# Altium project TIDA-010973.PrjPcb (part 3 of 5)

## Sheet TIDA-010973_SystemPower.SchDoc
size 431 x 279 mm; Date: Not shown in title block; ApprovedBy: Not shown in title block; CheckedBy: Not shown in title block; Author: Not shown in title block; CompanyName: Not shown in title block; Engineer: Not shown in title block; Organization: Not shown in title block; Address1: Not shown in title block; Address2: Not shown in title block; Address3: Not shown in title block; Address4: Not shown in title block; DocumentNumber: 2; Revision: Use project parameter SCH_Rev; SheetNumber: 7; SheetTotal: 15; PageSetup: Record=PageOptions¦CenterHorizontal=True¦CenterVertical=True¦PrintScale=1.00¦XCorrection=1.00¦YCorrection=1.00¦PrintKind=0¦BorderSize=5000000¦LeftOffset=0¦BottomOffset=0¦Orientation=2¦PaperLength=1000¦PaperWidth=1000¦Scale=100¦PaperSource=15¦PrintQuality=600¦MediaType=1¦DitherType=10¦PaperKind=Letter¦PrintScaleMode=1
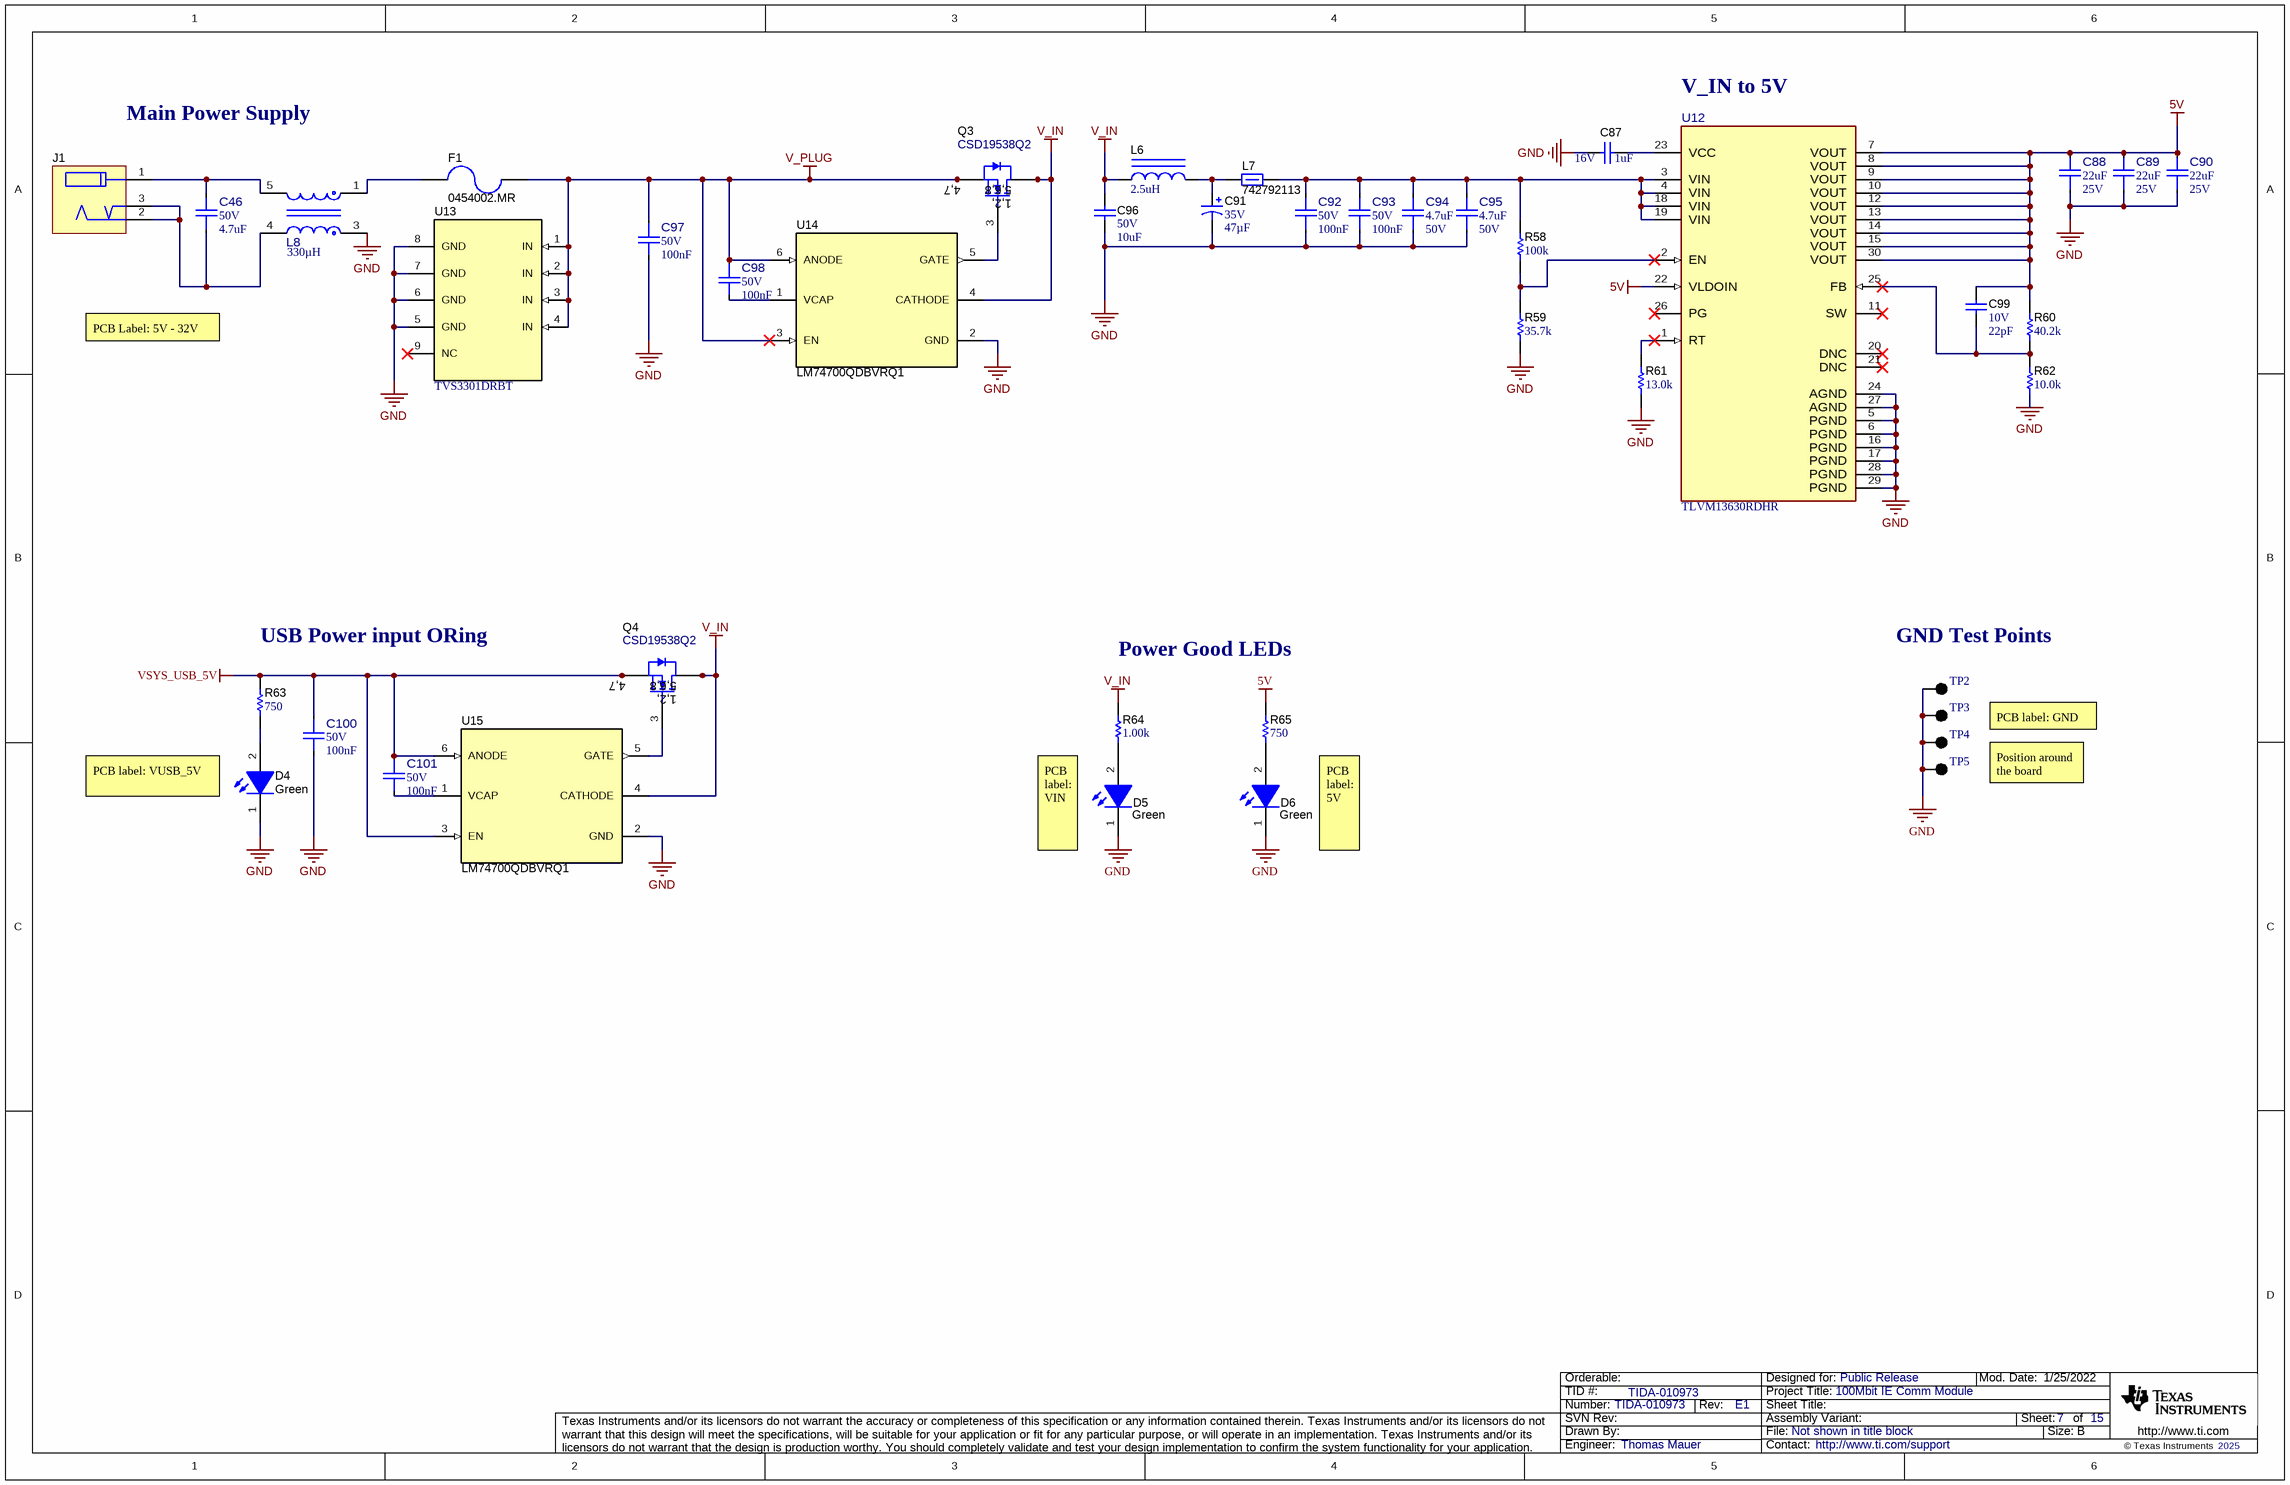
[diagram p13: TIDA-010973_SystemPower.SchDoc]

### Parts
C46  VDC_V: 50V  ValueDisplayed: 4.7uF  [FP-885012208094_1206-MFG]  (hidden comment: 885012208094)
C87  VDC_V: 16V  ValueDisplayed: 1uF  [0402L]  (hidden comment: EMK105BJ105KVHF)
C88  ValueDisplayed: 22uF  VDC_V: 25V  [FP-885012209074_1210-IPC_C]  (hidden comment: 885012209074)
C89  ValueDisplayed: 22uF  VDC_V: 25V  [FP-885012209074_1210-IPC_C]  (hidden comment: 885012209074)
C90  ValueDisplayed: 22uF  VDC_V: 25V  [FP-885012209074_1210-IPC_C]  (hidden comment: 885012209074)
C91  VDC_V: 35V  ValueDisplayed: 47µF  [Panasonic_SMT_630x580]  (hidden comment: EEE-FP1V470AP)
C92  VDC_V: 50V  ValueDisplayed: 100nF  [FP-885012205086_0402-IPC_C]  (hidden comment: 885012205086)
C93  VDC_V: 50V  ValueDisplayed: 100nF  [FP-885012205086_0402-IPC_C]  (hidden comment: 885012205086)
C94  ValueDisplayed: 4.7uF  VDC_V: 50V  [FP-885012209048_1210-IPC_C]  (hidden comment: 885012209048)
C95  ValueDisplayed: 4.7uF  VDC_V: 50V  [FP-885012209048_1210-IPC_C]  (hidden comment: 885012209048)
C96  VDC_V: 50V  ValueDisplayed: 10uF  [1210_270L]  (hidden comment: GRM32ER71H106KA12L)
C97  VDC_V: 50V  ValueDisplayed: 100nF  [FP-885012205086_0402-IPC_A]  (hidden comment: 885012205086)
C98  VDC_V: 50V  ValueDisplayed: 100nF  [FP-885012205086_0402-MFG]  (hidden comment: 885012205086)
C99  VDC_V: 10V  ValueDisplayed: 22pF  [0402L]  (hidden comment: 885012005009)
C100  VDC_V: 50V  ValueDisplayed: 100nF  [FP-885012205086_0402-IPC_C]  (hidden comment: 885012205086)
C101  VDC_V: 50V  ValueDisplayed: 100nF  [FP-885012205086_0402-IPC_C]  (hidden comment: 885012205086)
D4  value Green  [WL-SMCW_GREEN]  (hidden comment: 150060VS75000)
D5  value Green  [WL-SMCW_GREEN]  (hidden comment: 150060VS75000)
D6  value Green  [WL-SMCW_GREEN]  (hidden comment: 150060VS75000)
F1  0454002.MR  [SloBlo452]
J1  PJ-102AH  [CUI_PJ-102AH]  (value not drawn)
L6  ValueDisplayed: 2.5uH  [WE-TPC-S]  (hidden comment: 744031002)
L7  742792113  [1206L]
L8  Ind_H: 330µH  [FP-744212331_SMT_CMC_6MM5_3MM6-MFG]  (hidden comment: 744212331)
Q3  CSD19538Q2  [DQK0006C]
Q4  CSD19538Q2  [DQK0006C]
R58  ValueDisplayed: 100k  [0402L]  (hidden comment: CRCW0402100KFKED)
R59  ValueDisplayed: 35.7k  [0402L]  (hidden comment: CRCW040235K7FKED)
R60  ValueDisplayed: 40.2k  [0402L]  (hidden comment: CRCW040240K2FKED)
R61  ValueDisplayed: 13.0k  [0402L]  (hidden comment: CRCW040213K0FKED)
R62  ValueDisplayed: 10.0k  [0402L]  (hidden comment: CRCW040210K0DHEDP)
R63  ValueDisplayed: 750  [0402L]  (hidden comment: CRCW0402750RFKED)
R64  ValueDisplayed: 1.00k  [0402L]  (hidden comment: CRCW04021K00FKED)
R65  ValueDisplayed: 750  [0402L]  (hidden comment: CRCW0402750RFKED)
TP2  5011  [Keystone5011]  (value not drawn)
TP3  5011  [Keystone5011]  (value not drawn)
TP4  5011  [Keystone5011]  (value not drawn)
TP5  5011  [Keystone5011]  (value not drawn)
U12  TLVM13630RDHR  [RDH0030A-MFG]
U13  TVS3301DRBT  [DRB0008A]
U14  LM74700QDBVRQ1  [DBV0006A_L]
U15  LM74700QDBVRQ1  [DBV0006A_N]

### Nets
5V: C88.2 C89.2 C90.2 C99.1 R60.2 R65.2 U12.7(VOUT) U12.8(VOUT) U12.9(VOUT) U12.10(VOUT) U12.12(VOUT) U12.13(VOUT) U12.14(VOUT) U12.15(VOUT) U12.22(VLDOIN) U12.30(VOUT)
GND: C87.2 C88.1 C89.1 C90.1 C91.2(-) C92.1 C93.1 C94.1 C95.1 C96.2 C97.2 C100.2 D4.1(K) D5.1(K) D6.1(K) L8.3 R59.1 R61.1 R62.1 TP2.1 TP3.1 TP4.1 TP5.1 U12.5(PGND) U12.6(PGND) U12.16(PGND) U12.17(PGND) U12.24(AGND) U12.27(AGND) U12.28(PGND) U12.29(PGND) U13.5(GND) U13.6(GND) U13.7(GND) U13.8(GND) U14.2(GND) U15.2(GND)
V_IN: C96.1 L6.1 Q3.1(D) Q3.2(D) Q3.5(D) Q3.6(D) Q3.8(D) Q4.1(D) Q4.2(D) Q4.5(D) Q4.6(D) Q4.8(D) R64.2 U14.4(CATHODE) U15.4(CATHODE)
V_PLUG: C97.1 C98.1 F1.1 Q3.4(S) Q3.7(S) U13.1(IN) U13.2(IN) U13.3(IN) U13.4(IN) U14.3(EN) U14.6(ANODE)
VSYS_USB_5V: C100.1 C101.1 Q4.4(S) Q4.7(S) R63.2 U15.3(EN) U15.6(ANODE)
NetC46_1: C46.1 J1.2 J1.3 L8.4
NetC46_2: C46.2 J1.1 L8.5
NetC87_1: C87.1 U12.23(VCC)
NetC91_1: C91.1(+) L6.2 L7.1
NetC92_2: C92.2 C93.2 C94.2 C95.2 L7.2 R58.2 U12.3(VIN) U12.4(VIN) U12.18(VIN) U12.19(VIN)
NetC98_2: C98.2 U14.1(VCAP)
NetC99_2: C99.2 R60.1 R62.2 U12.25(FB)
NetC101_2: C101.2 U15.1(VCAP)
NetD4_2: D4.2(A) R63.1
NetD5_2: D5.2(A) R64.1
NetD6_2: D6.2(A) R65.1
NetF1_2: F1.2 L8.1
NetQ3_3: Q3.3(G) U14.5(GATE)
NetQ4_3: Q4.3(G) U15.5(GATE)
NetR58_1: R58.1 R59.2 U12.2(EN)
NetR61_2: R61.2 U12.1(RT)

Not connected (* = marked no-connect by the designer): U12 11(SW)* 20(DNC)* 21(DNC)* 26(PG)*; U13 9(NC)*

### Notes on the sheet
- V_IN to 5V
- Main Power Supply
- PCB Label: 5V - 32V
- (near R63) USB Power input ORing
- Power Good LEDs
- (near TP2) GND Test Points
- PCB label: GND
- PCB label: VUSB_5V
- Position around the board
- PCB label: VIN
- PCB label: 5V

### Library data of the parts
C46 = CMP-0088282-2: 4.7µF ±10% 50V Ceramic Capacitor X7R 1206 (3216 Metric); Manufacturer: Wurth Electronics; TempCo: 15%; Symbol Name: SYM-885012208094; SizeZ_mm: 1.9mm; AEC Qualified: No
C87 = CMP-0006347-2: CAP, CERM, 1 uF, 16 V, +/- 10%, X5R, 0402; Manufacturer: Taiyo Yuden; TaMin_C: -55°C; Polarized: N; SizeAreaWB_mm2: 3; Value1: Unknown; U/M: EA; Value: 1uF; TaMax_C: 85°C; SizeZ_mm: 0.6; SizeX_mm: 1; SizeY_mm: 0.5; Cap_Case: 0402; Cap_F: 1µF; AEC Category: Q200
C88-C90 = CMP-0096740-1: 22 µF ±10% 25V Ceramic Capacitor X7R 1210 (3225 Metric); Manufacturer: Wurth; AEC Qualified: No; Cap_F: 22µF; SizeZ_mm: 2.7mm; Value: 22µF; TempCo: 15%
C91 = CMP-0076702-1: CAP, AL, 47 µF, 35 V, +/- 20%, 0.26 ohm, AEC-Q200 Grade 2, SMD; Manufacturer: Panasonic; IRMS_A: 300mA; SizeAreaWB_mm2: 84.28; SizeArea_mm2: 51.48; AEC Qualified: Y; AEC Category: Q200; Value: 47uF; TaMax_C: 105°C; SizeZ_mm: 6.1; AEC Grade: 2; TaMin_C: -55°C; SizeY_mm: 6.6; U/M: EA; CompType: Capacitor; SizeX_mm: 7.8; ESR_ohm: 0.26; Cap_Case: 6.3x5.8mm
C92 C93 C97 C98 C100 C101 = CMP-0096737-1: 100 nF ±10% 50V Ceramic Capacitor X7R 0402 (1005 Metric); Manufacturer: Wurth; SizeZ_mm: 0.7mm; TempCo: 15%; AEC Qualified: No; Value: 100nF
C94 C95 = CMP-0096739-1: 4.7 µF ±10% 50V Ceramic Capacitor X7R 1210 (3225 Metric); Manufacturer: Wurth; TempCo: 15%; Cap_F: 4.7µF; AEC Qualified: No; SizeZ_mm: 2.7mm; Value: 4.7µF
C96 = CMP-0009226-3: CAP, CERM, 10 uF, 50 V, +/- 10%, X7R, 1210; Manufacturer: MuRata; TaMin_C: -55°C; Polarized: N; SizeAreaWB_mm2: 14.7; Value1: Unknown; U/M: EA; Value: 10uF; TaMax_C: 125°C; SizeZ_mm: 2.7; SizeX_mm: 3.2; SizeY_mm: 2.5; Cap_Case: 1210; SizeArea_mm2: 8; Cap_F: 10µF; AEC Category: Q200
C99 = CMP-0064912-2: CAP, CERM, 22 pF, 10 V,+/- 5%, C0G/NP0, 0402; Manufacturer: Wurth Elektronik; TaMin_C: -55°C; Polarized: N; SizeAreaWB_mm2: 3; Value1: Unknown; U/M: EA; Value: 22pF; TaMax_C: 125°C; SizeZ_mm: 0.6; SizeX_mm: 1; SizeY_mm: 0.5; Cap_Case: 0402; AEC Category: Q200
D4-D6 = CMP-0002894-2: LED, Green, SMD; Manufacturer: Wurth Elektronik; Type: AlInGaP; Value2: 2V; Io_A: 20mA; Value1: W
F1 = CMP-0003484-2: Fuse, 2 A, 125VAC/VDC, SMD; Manufacturer: Littelfuse; Irating_A: 2A; Interrupt_AC: 50A; VAC_V: 125V; Rtyp_Ohm: 62.5m; MeltingTyp: 8.2
J1 = CMP-0075222-1: DC POWER JACK, R/A, TH; Manufacturer: CUI Inc.; CNHeader: False; Current_A: 5A; Green_Lifecycle: Not Set; Gender: Male; Green_REACh: Incomplete; Voltage_V: 24V; Cert_UL: Y
L6 = CMP-0063784-1: Inductor, Shielded Drum Core, Ferrite, 2.5 uH, 1.25 A, 0.05 ohm, SMD; Manufacturer: Wurth Elektronik; Isat: 1.25A @ 35% inductance drop; Irms: 1.45A @ 30C rise; Green_Lifecycle: Active; SizeAreaWB_mm2: 23.04; DCR_ohm: 50m; Green_REACh: Passed; Value: 2.5uH; Imax_A: 1.25A; SizeZ_mm: 1.65; SizeX_mm: 3.8; SizeArea_mm2: 14.44; Ind_H: 2.5µH; AEC Category: Q200
L7 = CMP-0003112-1: Ferrite Bead, 120 ohm @ 100 MHz, 3 A, 1206; Manufacturer: Wurth Elektronik; Ztyp@1GHz_Ohm: 136.787; ZTyp@100MHz_Ohm: 120; SizeAreaWB_mm2: 10.92; DCR_ohm: 0.03; Value1: 0.03 ohm; Value: 120 ohm; Imax_A: 3A; SizeZ_mm: 1.35; SizeX_mm: 3.2; SizeY_mm: 1.6; SizeArea_mm2: 5.12
L8 = CMP-0127118-1: 330 µH @ 100 kHz 2 Line Common Mode Choke Surface Mount 2 kOhms @ 20 MHz 300mA DCR 300mOhm; Manufacturer: Wurth Electronics; AEC Qualified: No; DCR_ohm: 0.3; SizeZ_mm: 1.8mm; TaMax_C: +85°C; TaMin_C: -40°C; Test Frequency: 10kHz; Tolerance_%: 50%
Q3 Q4 = CMP-0000968-2: MOSFET, N-CH, 100 V, 4.5 A, DQK0006C (WSON-6); Alternate Manufacturer: None; Manufacturer: Texas Instruments; SizeZ_mm: 0.8; ChType: N; VdsMax_V: 100V; SizeX_mm: 2; SizeAreaWB_mm2: 9; Vgs_V: 20V; Value: 100V; SizeArea_mm2: 4; AEC Category: Q101; IdsMax_A: 4.5A; U/M: EA
R58 = CMP-0025950-3: RES, 100 k, 1%, 0.063 W, AEC-Q200 Grade 0, 0402; Manufacturer: Vishay-Dale; Power_W: 63mW; TempCo: 100 ppm/C; Value: 100k; EIA_Code: E96; SizeX_mm: 1; SizeY_mm: 0.5; SizeZ_mm: 0.6; Value2: 0.063W; AEC Qualified: Y; VDC_V: 50V; AEC Category: Q200; AEC Grade: 0
R59 = CMP-0026310-2: RES, 35.7 k, 1%, 0.063 W, AEC-Q200 Grade 0, 0402; Manufacturer: Vishay-Dale; Power_W: 63mW; TempCo: 100 ppm/C; Value_Code: 35k7; Value: 35.7k; EIA_Code: E96; SizeX_mm: 1; SizeY_mm: 0.5; SizeZ_mm: 0.6; Value2: 0.063W; AEC Qualified: Y; VDC_V: 50V; AEC Category: Q200; AEC Grade: 0
R60 = CMP-0026367-2: RES, 40.2 k, 1%, 0.063 W, AEC-Q200 Grade 0, 0402; Manufacturer: Vishay-Dale; Power_W: 63mW; TempCo: 100 ppm/C; Value_Code: 40k2; Value: 40.2k; EIA_Code: E96; SizeX_mm: 1; SizeY_mm: 0.5; SizeZ_mm: 0.6; Value2: 0.063W; AEC Qualified: Y; VDC_V: 50V; AEC Category: Q200; AEC Grade: 0
R61 = CMP-0026003-3: RES, 13.0 k, 1%, 0.063 W, AEC-Q200 Grade 0, 0402; Manufacturer: Vishay-Dale; Power_W: 63mW; TempCo: 100 ppm/C; Value_Code: 13k0; Value: 13.0k; EIA_Code: E96; Res_ohm: 13k; SizeX_mm: 1; SizeY_mm: 0.5; SizeZ_mm: 0.6; Value2: 0.063W; AEC Qualified: Y; VDC_V: 50V; AEC Category: Q200; AEC Grade: 0
R62 = CMP-0026769-2: RES, 10.0 k, 0.5%, 0.063 W, AEC-Q200 Grade 0, 0402; Manufacturer: Vishay-Dale; Power_W: 63mW; TempCo: 50 ppm/C; Value_Code: 10k0; Value: 10.0k; EIA_Code: E192; Res_ohm: 10k; SizeX_mm: 1; SizeY_mm: 0.5; SizeZ_mm: 0.6; Value2: 0.063W; AEC Qualified: Y; VDC_V: 50V; AEC Category: Q200; AEC Grade: 0
R63 R65 = CMP-0026542-2: RES, 750, 1%, 0.063 W, AEC-Q200 Grade 0, 0402; Manufacturer: Vishay-Dale; Power_W: 63mW; TempCo: 100 ppm/C; Value_Code: 750R; Value: 750; EIA_Code: E96; SizeX_mm: 1; SizeY_mm: 0.5; SizeZ_mm: 0.6; Value2: 0.063W; AEC Qualified: Y; VDC_V: 50V; AEC Grade: 0; AEC Category: Q200
R64 = CMP-0026071-3: RES, 1.00 k, 1%, 0.063 W, AEC-Q200 Grade 0, 0402; Manufacturer: Vishay-Dale; Power_W: 63mW; TempCo: 100 ppm/C; Value_Code: 1k00; Value: 1.00k; EIA_Code: E96; Res_ohm: 1k; SizeX_mm: 1; SizeY_mm: 0.5; SizeZ_mm: 0.6; Value2: 0.063W; AEC Qualified: Y; VDC_V: 50V; AEC Category: Q200; AEC Grade: 0
TP2-TP5 = CMP-0055148-2: Test Point, Multipurpose, Black, TH; Manufacturer: Keystone Electronics; CNHeader: FALSE; ContactFinish: Silver; Green_REACh: Passed; Green_Lifecycle: Active; CT: TRUE
U12 = CMP-0092030-4: 3-V to 36-V Input, 1-V to 6-V Output, 3-A Power Module; Manufacturer: Texas Instruments; Max Supply Voltage: 36V; Standoff Height: 0mm; AEC Qualified: No; CompType: IC; Min Supply Voltage: 3V; Switching Topology: Buck; AEC Category: Q200; TaMin_C: -40°C; TaMax_C: +105°C; Output Voltage: 1-6V; Switching Frequency: 200-2200kHz; Output Type: AdjustableProgrammable; SizeZ_mm: 1.9mm; Number Of Outputs: 1
U13 = CMP-0081714-3: 33 V Bidirectional Flat-Clamp Surge Protection Device, DRB0008A (VSON-8); Manufacturer: Texas Instruments; Alternate PartNumber: TVS3301DRBR; CompType: IC; SizeAreaWB_mm2: 16.0; SizeY_mm: 3.0; Rating: Catalog; AEC Category: Q200; AEC Qualified: N; SizeArea_mm2: 9.0; SizeZ_mm: 1.0
U14 U15 = CMP-0013281-4: Low Iq Always ON Smart Diode Controller, DBV0006A (SOT-23-6); Alternate PartNumber: LM74700QDBVTQ1; Manufacturer: Texas Instruments; SizeZ_mm: 1.45; SizeX_mm: 2.8; SizeY_mm: 2.9; SizeArea_mm2: 8.12; CompType: IC; SizeAreaWB_mm2: 14.82; AEC Category: Q200; AEC Qualified: Y

## Sheet TIDA-010973_SystemLED.SchDoc
size 431 x 279 mm; Date: Not shown in title block; ApprovedBy: Not shown in title block; CheckedBy: Not shown in title block; Author: Not shown in title block; CompanyName: Not shown in title block; Engineer: Not shown in title block; Organization: Not shown in title block; Address1: Not shown in title block; Address2: Not shown in title block; Address3: Not shown in title block; Address4: Not shown in title block; DocumentNumber: 2; Revision: Use project parameter SCH_Rev; SheetNumber: 10; SheetTotal: 15; PageSetup: Record=PageOptions¦CenterHorizontal=True¦CenterVertical=True¦PrintScale=1.00¦XCorrection=1.00¦YCorrection=1.00¦PrintKind=0¦BorderSize=5000000¦LeftOffset=0¦BottomOffset=0¦Orientation=2¦PaperLength=1000¦PaperWidth=1000¦Scale=100¦PaperSource=15¦PrintQuality=600¦MediaType=1¦DitherType=10¦PaperKind=Letter¦PrintScaleMode=1
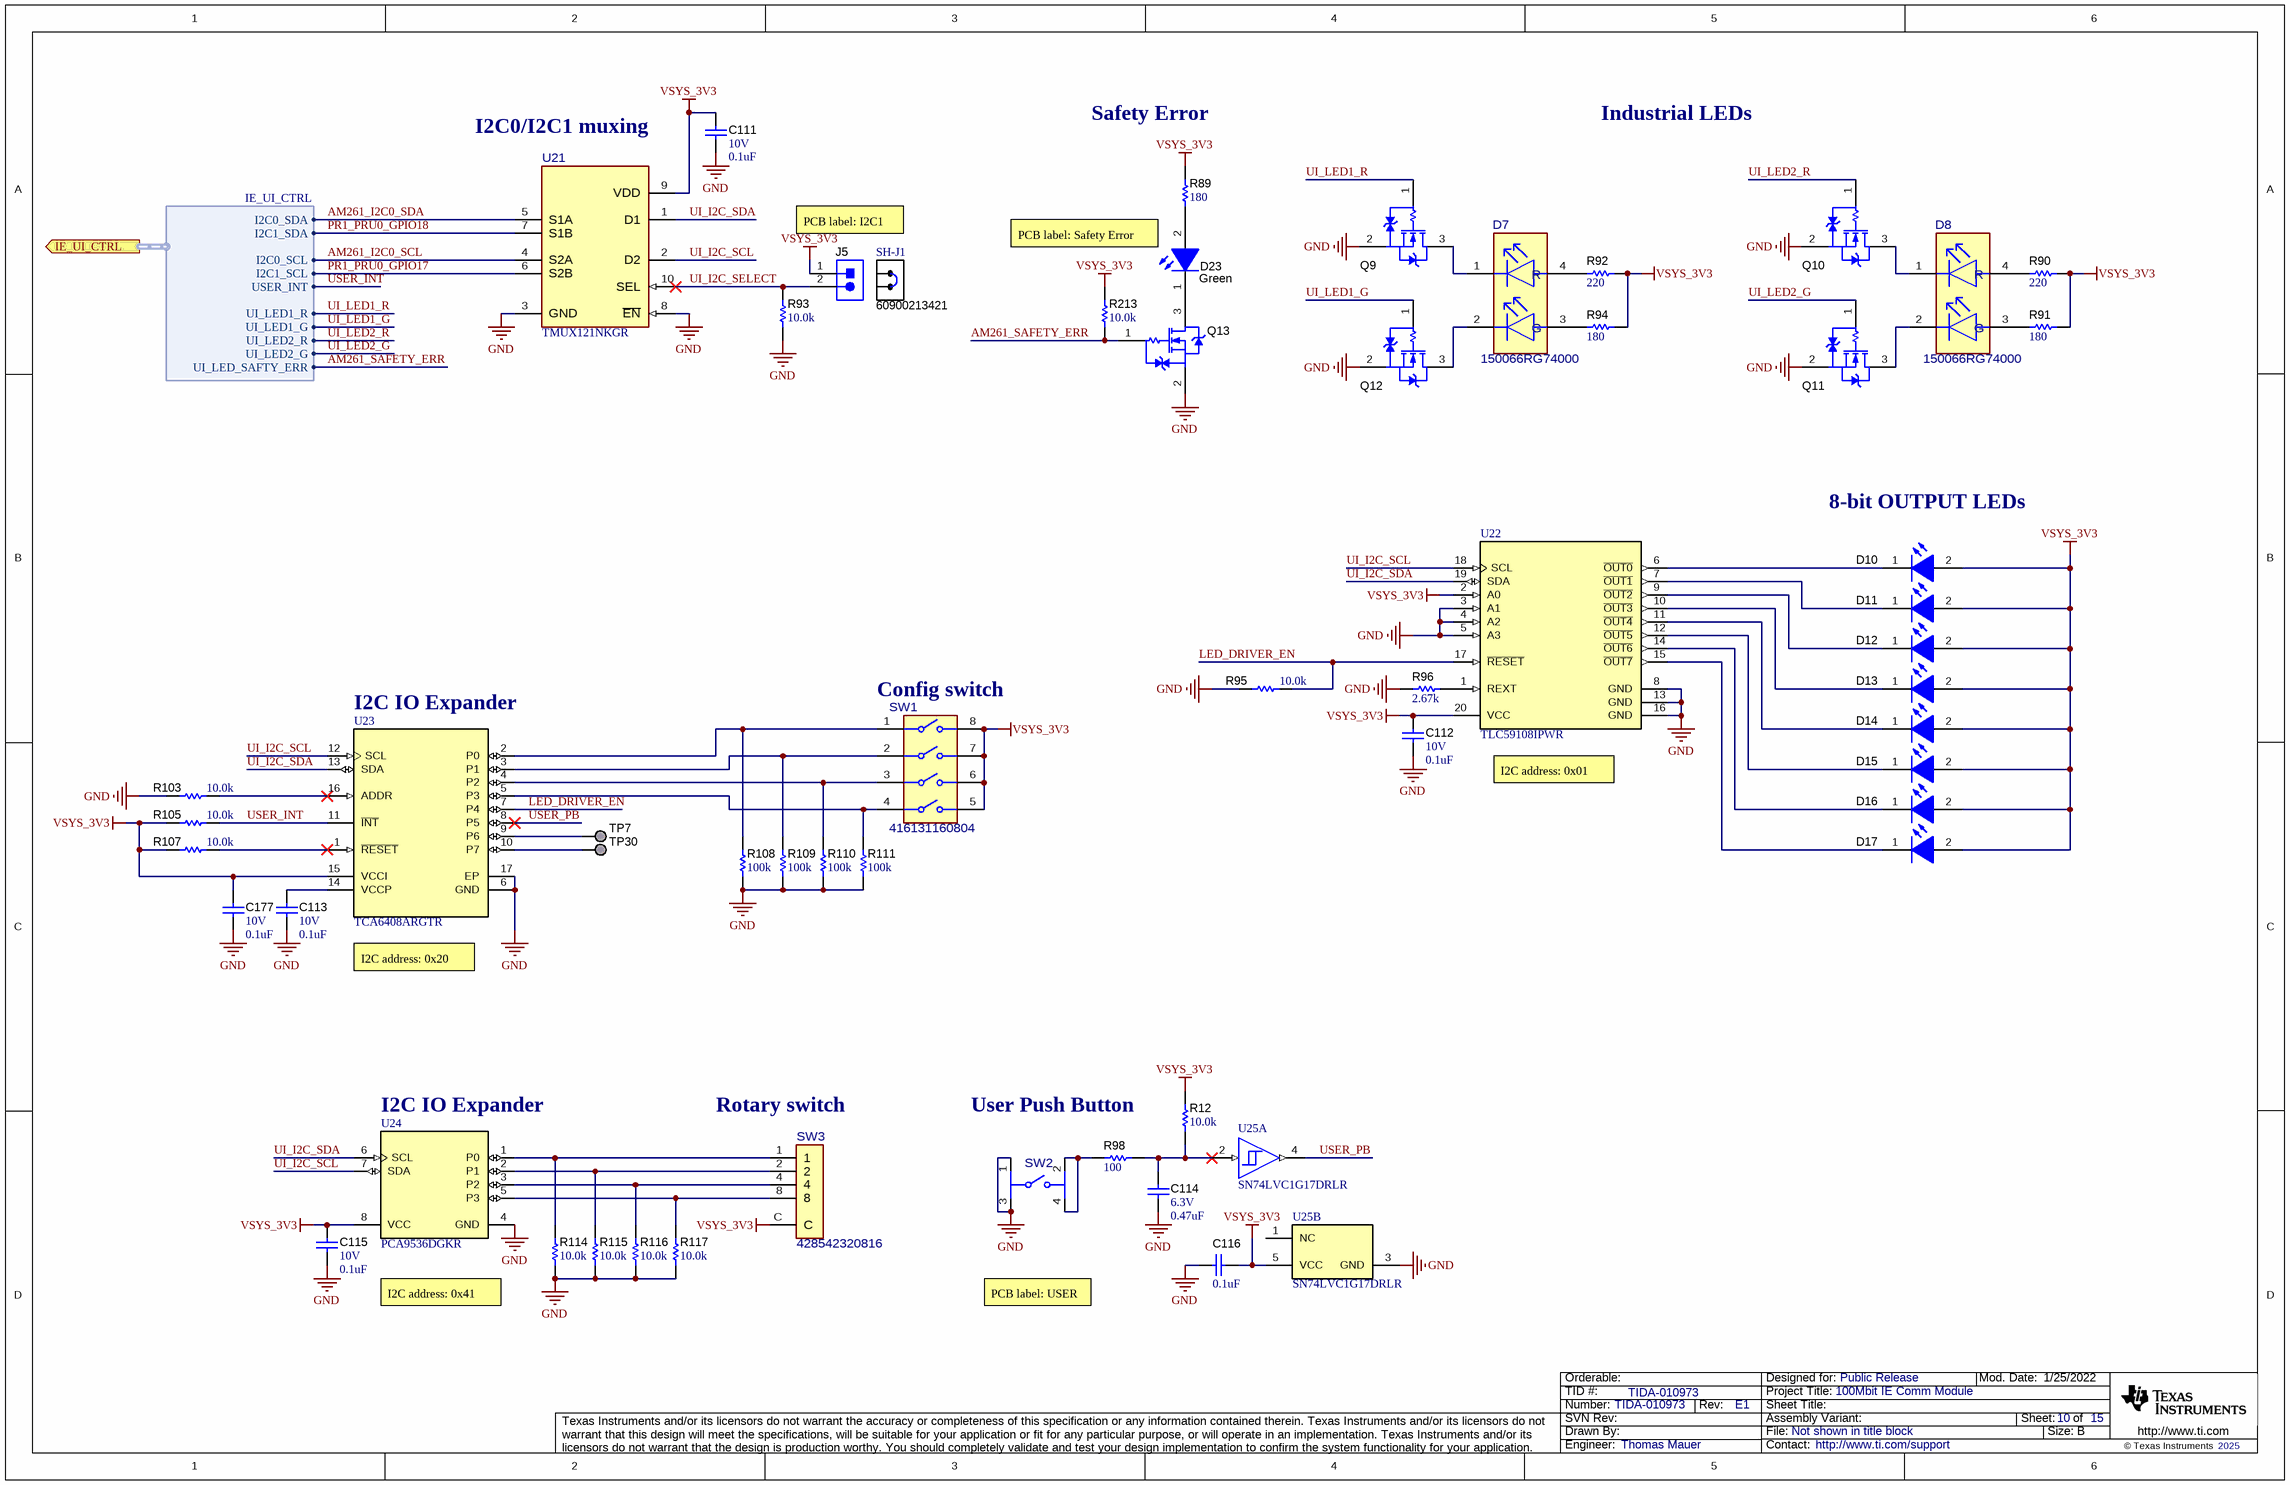
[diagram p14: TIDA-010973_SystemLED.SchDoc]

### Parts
C111  VDC_V: 10V  ValueDisplayed: 0.1uF  [0402L]  (hidden comment: 885012105010)
C112  VDC_V: 10V  ValueDisplayed: 0.1uF  [0402L]  (hidden comment: 885012105010)
C113  VDC_V: 10V  ValueDisplayed: 0.1uF  [0402L]  (hidden comment: 885012105010)
C114  VDC_V: 6.3V  ValueDisplayed: 0.47uF  [0402L]  (hidden comment: 04026D474KAT2A)
C115  VDC_V: 10V  ValueDisplayed: 0.1uF  [0402L]  (hidden comment: 885012105010)
C116  ValueDisplayed: 0.1uF  [0402L]  (hidden comment: 885012105010)
C177  VDC_V: 10V  ValueDisplayed: 0.1uF  [0402L]  (hidden comment: 885012105010)
D7  150066RG74000  [FP-150066RG74000_0606-MFG]
D8  150066RG74000  [FP-150066RG74000_0606-MFG]
D10  150060VS75000  [WL-SMCW_GREEN]  (value not drawn)
D11  150060VS75000  [WL-SMCW_GREEN]  (value not drawn)
D12  150060VS75000  [WL-SMCW_GREEN]  (value not drawn)
D13  150060VS75000  [WL-SMCW_GREEN]  (value not drawn)
D14  150060VS75000  [WL-SMCW_GREEN]  (value not drawn)
D15  150060VS75000  [WL-SMCW_GREEN]  (value not drawn)
D16  150060VS75000  [WL-SMCW_GREEN]  (value not drawn)
D17  150060VS75000  [WL-SMCW_GREEN]  (value not drawn)
D23  value Green  [WL-SMCW_GREEN]  (hidden comment: 150060VS75000)
J5  61300211121  [WURTH_61300211121]  (value not drawn)
Q9  CSD13383F4  [YJC0003A]  (value not drawn)
Q10  CSD13383F4  [YJC0003A]  (value not drawn)
Q11  CSD13383F4  [YJC0003A]  (value not drawn)
Q12  CSD13383F4  [YJC0003A]  (value not drawn)
Q13  CSD13383F4  [YJC0003A]  (value not drawn)
R12  ValueDisplayed: 10.0k  [0402L]  (hidden comment: CRCW040210K0FKED)
R89  ValueDisplayed: 180  [0402L]  (hidden comment: CRCW0402180RJNED)
R90  ValueDisplayed: 220  [0402L]  (hidden comment: CRCW0402220RJNTD)
R91  ValueDisplayed: 180  [0402L]  (hidden comment: CRCW0402180RJNED)
R92  ValueDisplayed: 220  [0402L]  (hidden comment: CRCW0402220RJNTD)
R93  ValueDisplayed: 10.0k  [0402L]  (hidden comment: CRCW040210K0FKED)
R94  ValueDisplayed: 180  [0402L]  (hidden comment: CRCW0402180RJNED)
R95  ValueDisplayed: 10.0k  [0402L]  (hidden comment: CRCW040210K0FKED)
R96  ValueDisplayed: 2.67k  [0402L]  (hidden comment: CRCW04022K67FKED)
R98  ValueDisplayed: 100  [0402L]  (hidden comment: CRCW0402100RFKED)
R103  ValueDisplayed: 10.0k  [0402L]  (hidden comment: CRCW040210K0FKED)
R105  ValueDisplayed: 10.0k  [0402L]  (hidden comment: CRCW040210K0FKED)
R107  ValueDisplayed: 10.0k  [0402L]  (hidden comment: CRCW040210K0FKED)
R108  ValueDisplayed: 100k  [0402L]  (hidden comment: CRCW0402100KFKED)
R109  ValueDisplayed: 100k  [0402L]  (hidden comment: CRCW0402100KFKED)
R110  ValueDisplayed: 100k  [0402L]  (hidden comment: CRCW0402100KFKED)
R111  ValueDisplayed: 100k  [0402L]  (hidden comment: CRCW0402100KFKED)
R114  ValueDisplayed: 10.0k  [0402L]  (hidden comment: CRCW040210K0FKED)
R115  ValueDisplayed: 10.0k  [0402L]  (hidden comment: CRCW040210K0FKED)
R116  ValueDisplayed: 10.0k  [0402L]  (hidden comment: CRCW040210K0FKED)
R117  ValueDisplayed: 10.0k  [0402L]  (hidden comment: CRCW040210K0FKED)
R213  ValueDisplayed: 10.0k  [0402L]  (hidden comment: CRCW040210K0FKED)
SH-J1  60900213421  [Wurth_60900213421]
SW1  416131160804  [FP-416131160804_SMT_SW-MFG]
SW2  434351045816  [FP-434351045816_SMT_SW_4MM7_4MM5-MFG]  (value not drawn)
SW3  428542320816  [FP-428542320816_SMT_SW_7MM4_7MM4-MFG]
TP7  TESTPOINT  [TP_25MIL-SMT]  (value not drawn)  (no BOM)
TP30  TESTPOINT  [TP_25MIL-SMT]  (value not drawn)  (no BOM)
U21  TMUX121NKGR  [NKG0010A-MFG]
U22  TLC59108IPWR  [PW0020A_N]
U23  TCA6408ARGTR  [RGT0016A]
U24  PCA9536DGKR  [DGK0008A_N]
U25  SN74LVC1G17DRLR  [DRL0005A]  (parts A,B of 2)

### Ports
IE_UI_CTRL (out, harness IE_UI_CTRL)

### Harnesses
IE_UI_CTRL: I2C0_SDA, I2C0_SCL, I2C1_SDA, I2C1_SCL, UI_LED1_R, UI_LED1_G, UI_LED_SAFTY_ERR, USER_INT, UI_LED2_R, UI_LED2_G

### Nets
GND: C111.2 C112.2 C113.2 C114.2 C115.2 C116.1 C177.2 Q9.2(S) Q10.2(S) Q11.2(S) Q12.2(S) Q13.2(S) R93.1 R95.1 R96.1 R103.1 R108.2 R109.2 R110.2 R111.2 R114.1 R115.1 R116.1 R117.1 SW2.1 SW2.3 U21.3(GND) U21.8(~{EN}) U22.3(A1) U22.4(A2) U22.5(A3) U22.8(GND) U22.13(GND) U22.16(GND) U23.6(GND) U23.17(EP) U24.4(GND) U25.3(GND)
VSYS_3V3: C111.1 C112.1 C115.1 C116.2 C177.1 D10.2(A) D11.2(A) D12.2(A) D13.2(A) D14.2(A) D15.2(A) D16.2(A) D17.2(A) J5.1 R12.2 R89.2 R90.1 R91.1 R92.1 R94.1 R105.1 R107.1 R213.2 SW1.5 SW1.6 SW1.7 SW1.8 SW3.C U21.9(VDD) U22.2(A0) U22.20(VCC) U23.15(VCCI) U24.8(VCC) U25.5(VCC)
AM261_I2C0_SCL: U21.4(S2A) ; port IE_UI_CTRL.I2C0_SCL  [project net AM261_I2C0.SCL]
AM261_I2C0_SDA: U21.5(S1A) ; port IE_UI_CTRL.I2C0_SDA  [project net AM261_I2C0.SDA]
AM261_SAFETY_ERR: Q13.1(G) R213.1 ; port IE_UI_CTRL.UI_LED_SAFTY_ERR
LED_DRIVER_EN: R95.2 U22.17(~{RESET}) U23.7(P4)
PR1_PRU0_GPIO17: U21.6(S2B) ; port IE_UI_CTRL.I2C1_SCL
PR1_PRU0_GPIO18: U21.7(S1B) ; port IE_UI_CTRL.I2C1_SDA
UI_I2C_SCL: U21.2(D2) U22.18(SCL) U23.12(SCL) U24.7(SDA)
UI_I2C_SDA: U21.1(D1) U22.19(SDA) U23.13(SDA) U24.6(SCL)
UI_I2C_SELECT: J5.2 R93.2 U21.10(SEL)
UI_LED1_G: Q12.1(G) ; port IE_UI_CTRL.UI_LED1_G
UI_LED1_R: Q9.1(G) ; port IE_UI_CTRL.UI_LED1_R
UI_LED2_G: Q11.1(G) ; port IE_UI_CTRL.UI_LED2_G
UI_LED2_R: Q10.1(G) ; port IE_UI_CTRL.UI_LED2_R
USER_INT: R105.2 U23.11(~{INT}) ; port IE_UI_CTRL.USER_INT
USER_PB: U23.8(P5) U25.4(Y)
NetC113_1: C113.1 U23.14(VCCP)
NetC114_1: C114.1 R12.1 R98.2 U25.2(A)
NetD7_1: D7.1(R_Cathode) Q9.3(D)
NetD7_2: D7.2(G_Cathode) Q12.3(D)
NetD7_3: D7.3(G_Anode) R94.2
NetD7_4: D7.4(R_Anode) R92.2
NetD8_1: D8.1(R_Cathode) Q10.3(D)
NetD8_2: D8.2(G_Cathode) Q11.3(D)
NetD8_3: D8.3(G_Anode) R91.2
NetD8_4: D8.4(R_Anode) R90.2
NetD10_1: D10.1(K) U22.6(~{OUT0})
NetD11_1: D11.1(K) U22.7(~{OUT1})
NetD12_1: D12.1(K) U22.9(~{OUT2})
NetD13_1: D13.1(K) U22.10(~{OUT3})
NetD14_1: D14.1(K) U22.11(~{OUT4})
NetD15_1: D15.1(K) U22.12(~{OUT5})
NetD16_1: D16.1(K) U22.14(~{OUT6})
NetD17_1: D17.1(K) U22.15(~{OUT7})
NetD23_1: D23.1(K) Q13.3(D)
NetD23_2: D23.2(A) R89.1
NetR96_2: R96.2 U22.1(REXT)
NetR98_1: R98.1 SW2.2 SW2.4
NetR103_2: R103.2 U23.16(ADDR)
NetR107_2: R107.2 U23.1(~{RESET})
NetR108_1: R108.1 SW1.1 U23.2(P0)
NetR109_1: R109.1 SW1.2 U23.3(P1)
NetR110_1: R110.1 SW1.3 U23.4(P2)
NetR111_1: R111.1 SW1.4 U23.5(P3)
NetR114_2: R114.2 SW3.1 U24.1(P0)
NetR115_2: R115.2 SW3.2 U24.2(P1)
NetR116_2: R116.2 SW3.4 U24.3(P2)
NetR117_2: R117.2 SW3.8 U24.5(P3)
NetTP7_1: TP7.1 U23.9(P6)
NetTP30_1: TP30.1 U23.10(P7)

Not connected (* = marked no-connect by the designer): U25 1(NC)

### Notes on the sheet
- I2C0/I2C1 muxing
- Safety Error
- Industrial LEDs
- PCB label: I2C1
- PCB label: Safety Error
- 8-bit OUTPUT LEDs
- (near SW1) Config switch
- (near U23) I2C IO Expander
- (near U22) I2C address: 0x01
- I2C address: 0x20
- (near U24) I2C IO Expander
- (near SW3) Rotary switch
- User Push Button
- I2C address: 0x41
- PCB label: USER

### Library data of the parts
C111-C113 C115 C177 = CMP-0006221-2: CAP, CERM, 0.1 uF, 10 V, +/- 20%, X5R, 0402; Manufacturer: Wurth Elektronik; TaMin_C: -55°C; Polarized: N; SizeAreaWB_mm2: 3; Value1: Unknown; U/M: EA; Value: 0.1uF; TaMax_C: 85°C; SizeZ_mm: 0.6; SizeX_mm: 1; SizeY_mm: 0.5; Cap_Case: 0402; Cap_F: 100nF; AEC Category: Q200
C114 = CMP-0006199-2: CAP, CERM, 0.47 uF, 6.3 V, +/- 10%, X5R, 0402; Manufacturer: AVX; TaMin_C: -55°C; Polarized: N; SizeAreaWB_mm2: 3; Value1: Unknown; U/M: EA; Value: 0.47uF; TaMax_C: 85°C; SizeZ_mm: 0.6; SizeX_mm: 1; SizeY_mm: 0.5; Cap_Case: 0402; Cap_F: 470nF; AEC Category: Q200
C116 = CMP-0006221-2: CAP, CERM, 0.1 uF, 10 V, +/- 20%, X5R, 0402; Manufacturer: Wurth Elektronik; TaMin_C: -55°C; Polarized: N; SizeAreaWB_mm2: 3; Value1: Unknown; U/M: EA; Value: 0.1uF; TaMax_C: 85°C; SizeZ_mm: 0.6; SizeX_mm: 1; SizeY_mm: 0.5; Cap_Case: 0402; Value2: 10V; Cap_F: 100nF; AEC Category: Q200
D7 D8 = CMP-0125609-1: Green, Red 520nm Green, 625nm Red LED Indication - Discrete 3.2V Green, 2V Red 0606 (1616 Metric); Manufacturer: Wurth; Angle: 130°; Color: Red, Green; LambdaD: 625/520nm; LambdaP: 630/515nm; SizeZ_mm: 0.8mm; Tjmax_C: 95°C; Vr_V: 5V; AEC Qualified: No; Forward Current: 20mA; Led Orientation: Top View; Luminous Intensity: 300/560mcd
D10-D17 D23 = CMP-0002894-2: as D4-D6 on sheet TIDA-010973_SystemPower
J5 = CMP-0054794-2: Header, 2.54 mm, 2x1, Gold, TH; Manufacturer: Wurth Elektronik; Shrouded: N; Gender: Male; Green_REACh: Passed; Pitch_mm: 2.54; Green_Lifecycle: Active; Row_Count: 1; Cert_UL: Y
Q9-Q13 = CMP-0000198-1: MOSFET, N-CH, 12 V, 2.9 A, YJC0003A (PICOSTAR-3); Alternate Manufacturer: None; Manufacturer: Texas Instruments; SizeZ_mm: 0.35; ChType: N; Value2: 2 nC; Value1: 0.04; VdsMax_V: 12V; SizeX_mm: 1.035; SizeY_mm: 0.635; Vgs_V: 10V; Value: 12V; Rdson45_ohm: 0.044; SizeArea_mm2: 0.657225; AEC Category: Q101; IdsMax_A: 2.9A; SizeAreaWB_mm2: 3.327225; U/M: EA; QgTyp_nC: 2
R12 R93 R95 R103 R105 R107 R114-R117 R213 = CMP-0025958-3: RES, 10.0 k, 1%, 0.063 W, AEC-Q200 Grade 0, 0402; Manufacturer: Vishay-Dale; Power_W: 63mW; TempCo: 100 ppm/C; Value_Code: 10k0; Value: 10.0k; EIA_Code: E96; Res_ohm: 10k; SizeX_mm: 1; SizeY_mm: 0.5; SizeZ_mm: 0.6; Value2: 0.063W; AEC Qualified: Y; VDC_V: 50V; AEC Category: Q200; AEC Grade: 0
R89 R91 R94 = CMP-0026849-3: RES, 180, 5%, 0.063 W, AEC-Q200 Grade 0, 0402; Manufacturer: Vishay-Dale; Power_W: 63mW; TempCo: 200 ppm/C; Value_Code: 180R; Value: 180; EIA_Code: E24; SizeX_mm: 1; SizeY_mm: 0.5; SizeZ_mm: 0.6; Value2: 0.063W; AEC Qualified: Y; VDC_V: 50V; AEC Category: Q200; AEC Grade: 0
R90 R92 = CMP-0081786-1: RES, 220, 5%, 0.063 W, AEC-Q200 Grade 0, 0402; Manufacturer: Vishay-Dale; Power_W: 63mW; TempCo: 200 ppm/C; SizeAreaWB_mm2: 3; Value_Code: 220R; Value: 220; EIA_Code: E24; SizeX_mm: 1; SizeY_mm: 0.5; SizeZ_mm: 0.6; Value2: 0.063W; AEC Qualified: Y; VDC_V: 50V; AEC Grade: 0; AEC Category: Q200
R96 = CMP-0026240-2: RES, 2.67 k, 1%, 0.063 W, AEC-Q200 Grade 0, 0402; Manufacturer: Vishay-Dale; Power_W: 63mW; TempCo: 100 ppm/C; Value_Code: 2k67; Value: 2.67k; EIA_Code: E96; SizeX_mm: 1; SizeY_mm: 0.5; SizeZ_mm: 0.6; Value2: 0.063W; AEC Qualified: Y; VDC_V: 50V; AEC Category: Q200; AEC Grade: 0
R98 = CMP-0025951-3: RES, 100, 1%, 0.063 W, AEC-Q200 Grade 0, 0402; Manufacturer: Vishay-Dale; Power_W: 63mW; TempCo: 100 ppm/C; Value_Code: 100R; Value: 100; EIA_Code: E96; SizeX_mm: 1; SizeY_mm: 0.5; SizeZ_mm: 0.6; Value2: 0.063W; AEC Qualified: Y; VDC_V: 50V; AEC Category: Q200; AEC Grade: 0
R108-R111 = CMP-0025950-3: as R58 on sheet TIDA-010973_SystemPower
SH-J1 = CMP-0003761-2: Shunt, 2.54mm, Gold, Black; Manufacturer: Wurth Elektronik
SW1 = CMP-0093176-1: Dip Switch SPST 4 Position Surface Mount Slide (Standard) Actuator 25mA 24VDC; Manufacturer: Wurth; PositionCount: 4; Electromechanical Life: 1000Cycles; Circuit: 4PST; Coil Resistance_ohm: 100mΩ; VDC_V: 24V; Standoff Height: 0mm; SizeZ_mm: 2.65mm; AEC Qualified: No
SW2 = CMP-0093456-1: Tactile Switch SPST-NO Side Actuated Surface Mount, Right Angle; Manufacturer: Wurth Electronics; Operating Force: 160gf; SizeZ_mm: 1.75mm; AEC Qualified: No; Electromechanical Life: 200000Cycles; VDC_V: 12V; Contact Current Rating: 50mA; Coil Resistance_ohm: 100mΩ
SW3 = CMP-0124547-1: Dip Switch Hexadecimal 16 Position Surface Mount Rotary for Tool Actuator 100mA 42VDC; Manufacturer: Wurth; CurrentRating_mA: 400mA; SizeZ_mm: 3.95mm; VDC_V: 42V; AEC Qualified: No; Coil Resistance_ohm: 80mΩ; Electromechanical Life: 25000Cycles; Operating Force: 150gf
TP7 TP30 = CMP-0078143-4: TEST POINT.  No entry in BOM.
U21 = CMP-0122684-1: 2-pF, 3.3-V, 2:1 (SPDT), 2-channel, switch with 1.8-V compatible logic; Manufacturer: Texas Instruments; SizeZ_mm: 0.55mm; AEC Qualified: No; -3Db Bandwith: 3GHz; Max Supply Voltage: 3.6V; Min Supply Voltage: 3V; Mux Demux Ratio: 2:4; Nominal Supply Current: 1.3-11uA; On State Resistance: 3.9Ω; PositionCount: 1; Standoff Height: 0mm; TaMax_C: +125°C; TaMin_C: -40°C
U22 = CMP-0034642-1: 8-Bit Fast Mode Plus (FM+) I2C Bus Constant-Current LED Sink Driver, 3 to 5.5 V, -40 to 85 degC, 20-pin SOP (PW20), Green (RoHS & no Sb/Br); Manufacturer: Texas Instruments; SubFamily: LED Driver; Vin(Min)(V): 3; Iout(Max)(A): 0.12; Vin(Max)(V): 5.5
U23 = CMP-0043157-2: Low-Voltage 8-Bit I2C and SMBus I/O Expander, 1.65 to 5.5 V, -40 to 85 degC, 16-pin QFN (RGT), Green (RoHS & no Sb/Br); Manufacturer: Texas Instruments; # of I/Os: 8; I2C Address: 0100 00x; Reset Input: Yes; Max Frequency(kHz): 400; VCC(Max)(V): 5.5; SubFamily: I2C IO Expander; VCC(Min)(V): 1.65
U24 = CMP-0043237-2: Remote 4-Bit I2C and SMBus I/O Expander With Configuration Registers, DGK0008A (VSSOP-8); Manufacturer: Texas Instruments; SubFamily: I2C IO Expander; Max Frequency(kHz): 400; Eco-Plan: Green (RoHS & no Sb/Br); Configuration Registers: Yes; I2C Address: 1000 001; VCC(Max)(V): 5.5; # of I/Os: 4; Vcc range(V): 2.3 to 5.5; VCC(Min)(V): 2.3; AEC Category: Q200; AEC Qualified: N; CompType: IC; SizeAreaWB_mm2: 23.6; SizeArea_mm2: 14.7; SizeX_mm: 4.9; SizeY_mm: 3; SizeZ_mm: 1.1
U25 = CMP-0051707-3: Single Schmitt-Trigger Buffer, DRL0005A, LARGE T&R; Manufacturer: Texas Instruments; Voltage(Nom)(V): 1.8,2.5,3.3,5; Schmitt Trigger: Yes; 3-State Output: No; ICC @ Nom Voltage(Max)(mA): 0.01; Input Type: CMOS/TTL; Output Type: CMOS; F @ Nom Voltage(Max)(Mhz): 150; Sub-Family: Non-Inverting Buffer/Driver; VCC(Min)(V): 1.65; Technology Family: LVC; Output Drive (IOL/IOH)(Max)(mA): 32/-32; VCC(Max)(V): 5.5; Logic: True; Bits(#): 1; Rating: Catalog; tpd @ Nom Voltage(Max)(ns): 11,6.5,5.5,5; AEC Category: Q200; AEC Qualified: N; CompType: IC; SizeX_mm: 1.6; SizeZ_mm: 0.6

## Sheet TIDA-010973_USB2.SchDoc
size 431 x 279 mm; Date: Not shown in title block; ApprovedBy: Not shown in title block; CheckedBy: Not shown in title block; Author: Not shown in title block; CompanyName: Not shown in title block; Engineer: Not shown in title block; Organization: Not shown in title block; Address1: Not shown in title block; Address2: Not shown in title block; Address3: Not shown in title block; Address4: Not shown in title block; DocumentNumber: 2; Revision: Use project parameter SCH_Rev; SheetNumber: 13; SheetTotal: 15
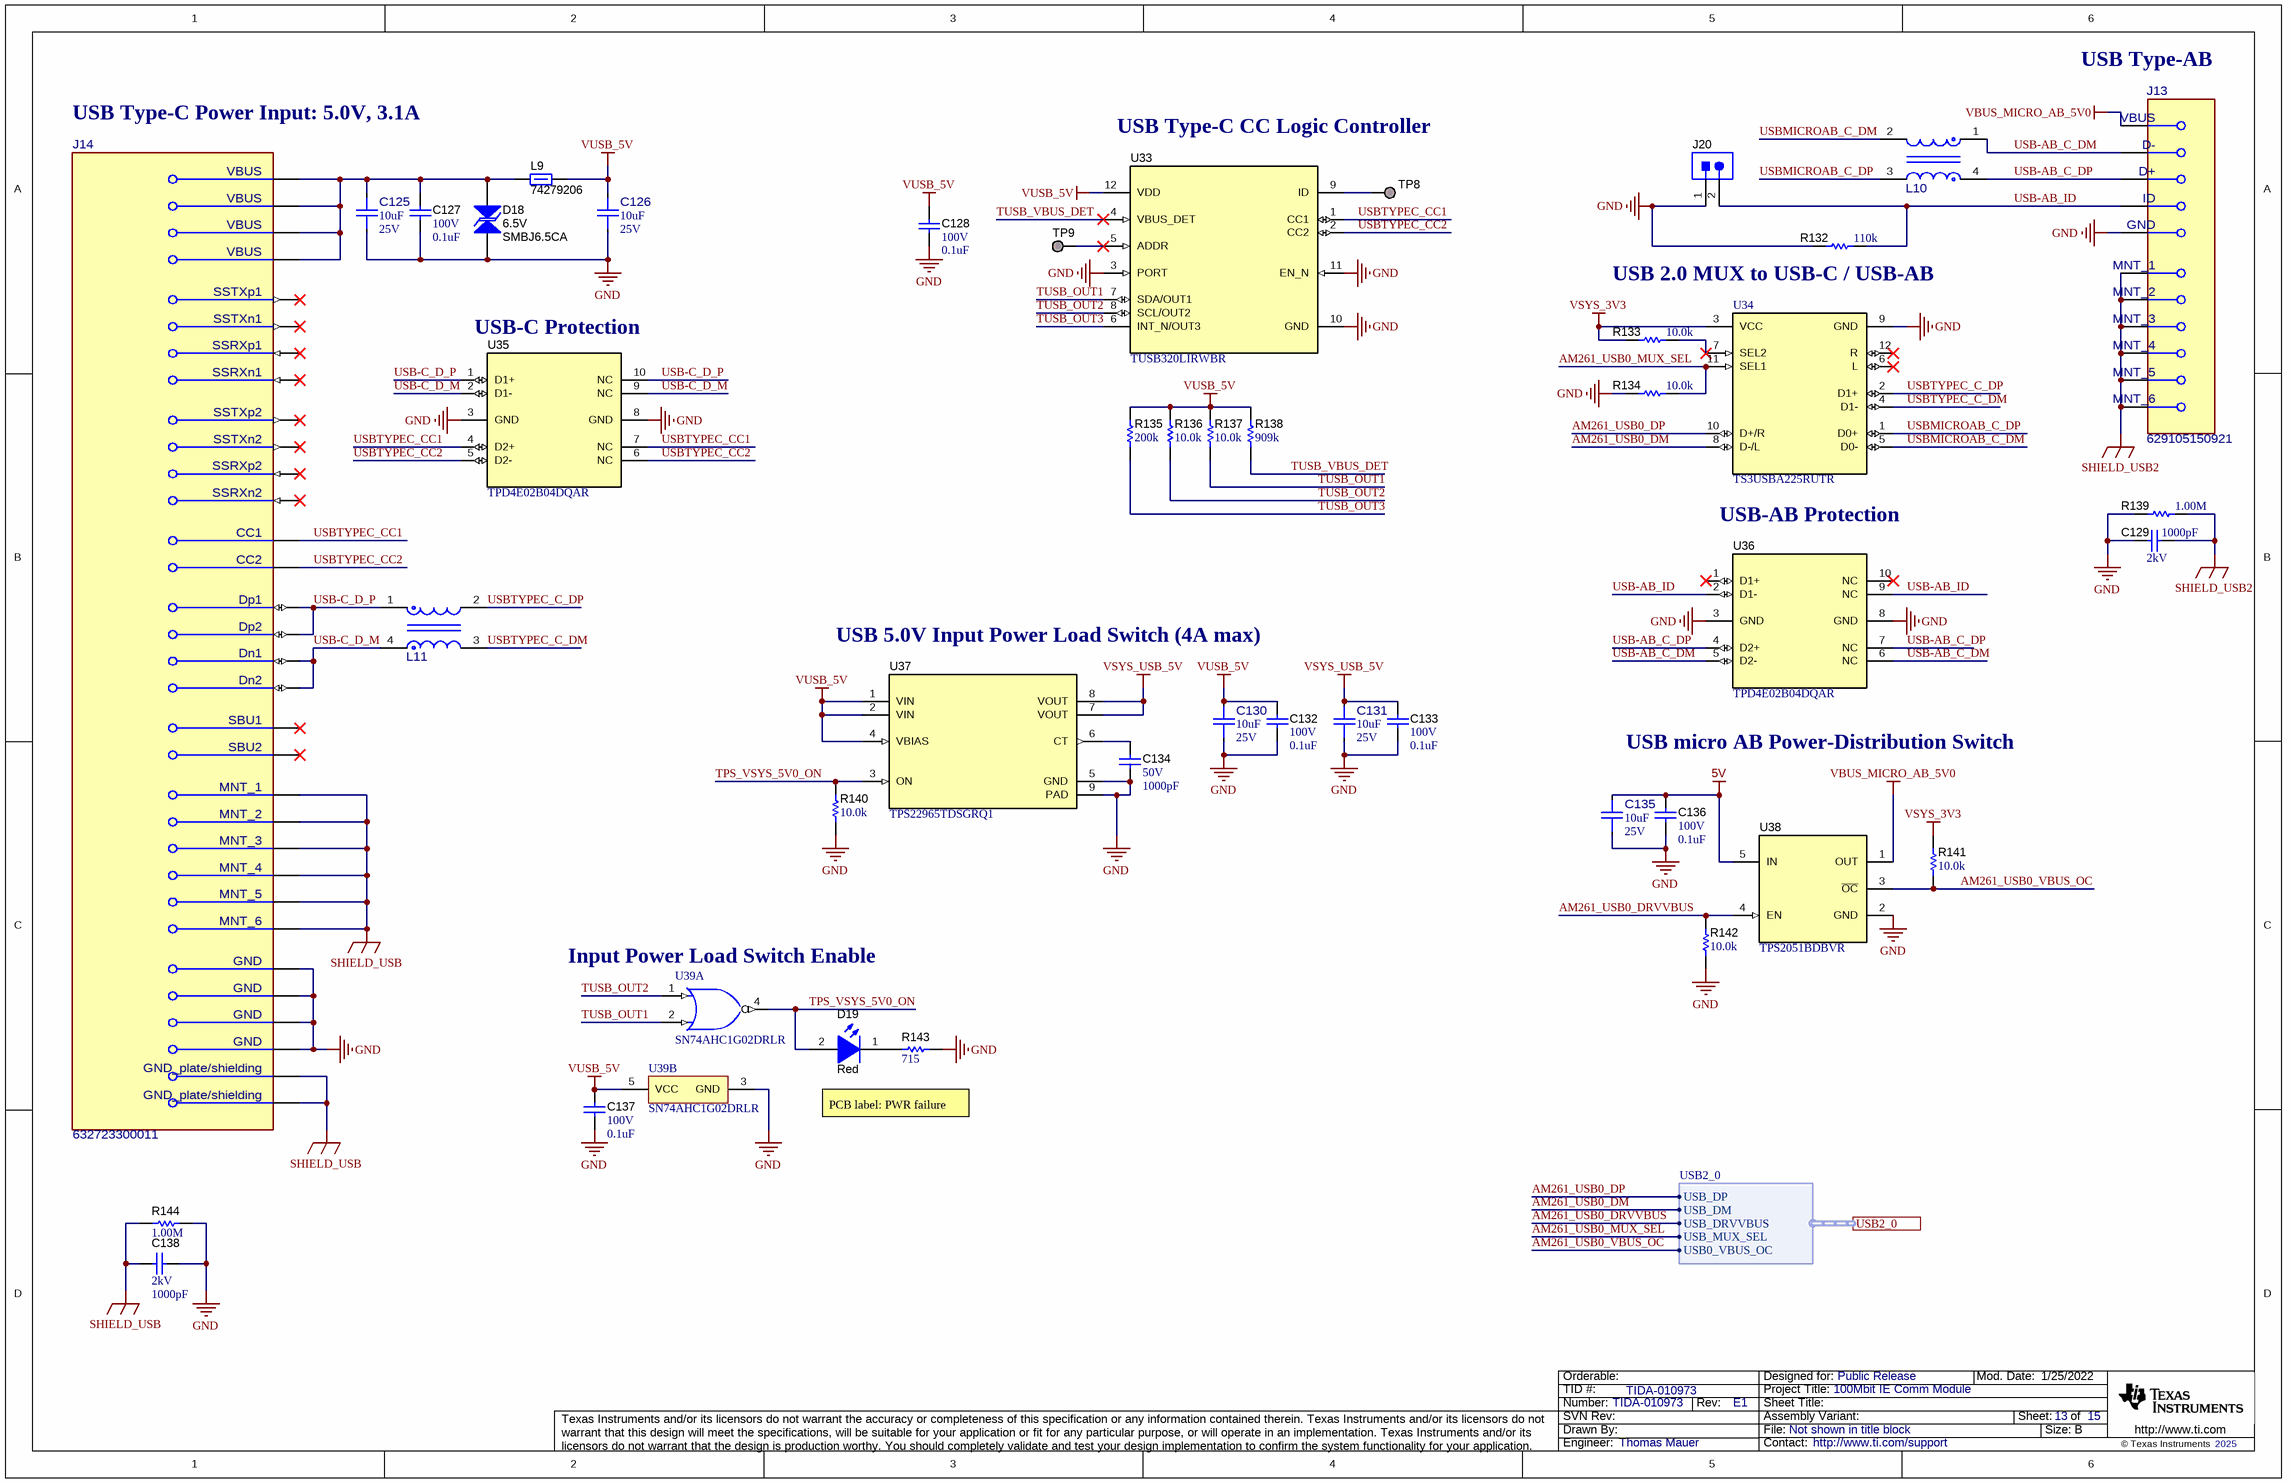
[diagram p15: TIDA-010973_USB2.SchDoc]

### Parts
C125  ValueDisplayed: 10uF  VDC_V: 25V  [FP-885012106031_0603-IPC_C]  (hidden comment: 885012106031)
C126  ValueDisplayed: 10uF  VDC_V: 25V  [FP-885012106031_0603-IPC_C]  (hidden comment: 885012106031)
C127  VDC_V: 100V  ValueDisplayed: 0.1uF  [0402L]  (hidden comment: GRM155R62A104KE14D)
C128  VDC_V: 100V  ValueDisplayed: 0.1uF  [0402L]  (hidden comment: GRM155R62A104KE14D)
C129  VDC_V: 2kV  ValueDisplayed: 1000pF  [1812_254]  (hidden comment: 1812GC102KA1)
C130  ValueDisplayed: 10uF  VDC_V: 25V  [FP-885012106031_0603-IPC_C]  (hidden comment: 885012106031)
C131  ValueDisplayed: 10uF  VDC_V: 25V  [FP-885012106031_0603-IPC_C]  (hidden comment: 885012106031)
C132  VDC_V: 100V  ValueDisplayed: 0.1uF  [0402L]  (hidden comment: GRM155R62A104KE14D)
C133  VDC_V: 100V  ValueDisplayed: 0.1uF  [0402L]  (hidden comment: GRM155R62A104KE14D)
C134  VDC_V: 50V  ValueDisplayed: 1000pF  [0402L]  (hidden comment: GCM155R71H102KA37D)
C135  ValueDisplayed: 10uF  VDC_V: 25V  [FP-885012106031_0603-IPC_C]  (hidden comment: 885012106031)
C136  VDC_V: 100V  ValueDisplayed: 0.1uF  [0402]  (hidden comment: GRM155R62A104KE14D)
C137  VDC_V: 100V  ValueDisplayed: 0.1uF  [0402L]  (hidden comment: GRM155R62A104KE14D)
C138  VDC_V: 2kV  ValueDisplayed: 1000pF  [1812_254]  (hidden comment: 1812GC102KA1)
D18  SMBJ6.5CA  value 6.5V  [SMB-Bi]
D19  value Red  [WL-SMCW_RED]  (hidden comment: 150060RS75000)
J13  629105150921  [FP-629105150921_CONN_PTH_USB_8MM0_5MM6-MFG]
J14  632723300011  [FP-632723300011_CONN_USB_8MM74_11MM20-MFG]
J20  61300211121  [WURTH_61300211121]  (value not drawn)
L9  74279206  [0805L]
L10  744233900  [FP-744233900_SMT4-MFG]  (value not drawn)
L11  744233900  [FP-744233900_SMT4-MFG]  (value not drawn)
R132  ValueDisplayed: 110k  [0402L]  (hidden comment: CRCW0402110KFKED)
R133  ValueDisplayed: 10.0k  [0402L]  (hidden comment: CRCW040210K0FKED)
R134  ValueDisplayed: 10.0k  [0402L]  (hidden comment: CRCW040210K0FKED)
R135  ValueDisplayed: 200k  [0402L]  (hidden comment: CRCW0402200KFKED)
R136  ValueDisplayed: 10.0k  [0402L]  (hidden comment: CRCW040210K0FKED)
R137  ValueDisplayed: 10.0k  [0402L]  (hidden comment: CRCW040210K0FKED)
R138  ValueDisplayed: 909k  [0402L]  (hidden comment: CRCW0402909KFKED)
R139  ValueDisplayed: 1.00M  [2010]  (hidden comment: CRCW20101M00FKEF)
R140  ValueDisplayed: 10.0k  [0402L]  (hidden comment: CRCW040210K0FKED)
R141  ValueDisplayed: 10.0k  [0402]  (hidden comment: CRCW040210K0FKED)
R142  ValueDisplayed: 10.0k  [0402]  (hidden comment: CRCW040210K0FKED)
R143  ValueDisplayed: 715  [0402L]  (hidden comment: CRCW0402715RFKED)
R144  ValueDisplayed: 1.00M  [2010]  (hidden comment: CRCW20101M00FKEF)
TP8  TESTPOINT  [TP_25MIL-SMT]  (value not drawn)  (no BOM)
TP9  TESTPOINT  [TP_25MIL-SMT]  (value not drawn)  (no BOM)
U33  TUSB320LIRWBR  [RWB0012A]
U34  TS3USBA225RUTR  [RUT0012A]
U35  TPD4E02B04DQAR  [DQA0010A]
U36  TPD4E02B04DQAR  [DQA0010A]
U37  TPS22965TDSGRQ1  [DSG0008B]
U38  TPS2051BDBVR  [DBV0005A_N]
U39  SN74AHC1G02DRLR  [DRL0005A]  (parts A,B of 2)

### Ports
USB2_0 (harness USB2_0)

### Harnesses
USB2_0: USB_DM, USB_DP, USB_DRVVBUS, USB_MUX_SEL, USB0_VBUS_OC

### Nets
5V: C135.2 C136.1 U38.5(IN)
GND: C125.1 C126.1 C127.2 C128.2 C129.2 C130.1 C131.1 C132.2 C133.2 C134.1 C135.1 C136.2 C137.2 C138.1 D18.1 J13.5(GND) J14.A1(GND) J14.A12(GND) J14.B1(GND) J14.B12(GND) J20.1 R132.1 R134.2 R139.1 R140.1 R142.2 R143.1 R144.2 U33.3(PORT) U33.10(GND) U33.11(EN_N) U34.9(GND) U35.3(GND) U35.8(GND) U36.3(GND) U36.8(GND) U37.5(GND) U37.9(PAD) U38.2(GND) U39.3(GND)
SHIELD_USB: C138.2 J14.1(GND_plate/shielding) J14.2(GND_plate/shielding) J14.3(MNT_1) J14.4(MNT_2) J14.5(MNT_3) J14.6(MNT_4) J14.7(MNT_5) J14.8(MNT_6) R144.1
SHIELD_USB2: C129.1 J13.6(MNT_1) J13.7(MNT_2) J13.8(MNT_3) J13.9(MNT_4) J13.10(MNT_5) J13.11(MNT_6) R139.2
VBUS_MICRO_AB_5V0: J13.1(VBUS) U38.1(OUT)
VSYS_3V3: R133.2 R141.1 U34.3(VCC)
VSYS_USB_5V: C131.2 C133.1 U37.7(VOUT) U37.8(VOUT)
VUSB_5V: C126.2 C128.1 C130.2 C132.1 C137.1 L9.2 R135.2 R136.2 R137.2 R138.2 U33.12(VDD) U37.1(VIN) U37.2(VIN) U37.4(VBIAS) U39.5(VCC)
AM261_USB0_DM: U34.8(D-/L) ; port USB2_0.USB_DM  [project net AM261_USB0_D_N]
AM261_USB0_DP: U34.10(D+/R) ; port USB2_0.USB_DP  [project net AM261_USB0_D_P]
AM261_USB0_DRVVBUS: R142.1 U38.4(EN) ; port USB2_0.USB_DRVVBUS
AM261_USB0_MUX_SEL: R134.1 U34.11(SEL1) ; port USB2_0.USB_MUX_SEL
AM261_USB0_VBUS_OC: R141.2 U38.3(~{OC}) ; port USB2_0.USB0_VBUS_OC
TPS_VSYS_5V0_ON: D19.2(A) R140.2 U37.3(ON) U39.4(Y)
TUSB_OUT1: R137.1 U33.7(SDA/OUT1) U39.2(B)
TUSB_OUT2: R136.1 U33.8(SCL/OUT2) U39.1(A)
TUSB_OUT3: R135.1 U33.6(INT_N/OUT3)
TUSB_VBUS_DET: R138.1 U33.4(VBUS_DET)
USB-AB_C_DM: J13.2(D-) L10.1 U36.5(D2-) U36.6(NC)
USB-AB_C_DP: J13.3(D+) L10.4 U36.4(D2+) U36.7(NC)
USB-AB_ID: J13.4(ID) J20.2 R132.2 U36.2(D1-) U36.9(NC)
USB-C_D_M: J14.A7(Dn1) J14.B7(Dn2) L11.4 U35.2(D1-) U35.9(NC)
USB-C_D_P: J14.A6(Dp1) J14.B6(Dp2) L11.1 U35.1(D1+) U35.10(NC)
USBMICROAB_C_DM: L10.2 U34.5(D0-)
USBMICROAB_C_DP: L10.3 U34.1(D0+)
USBTYPEC_C_DM: L11.3 U34.4(D1-)
USBTYPEC_C_DP: L11.2 U34.2(D1+)
USBTYPEC_CC1: J14.A5(CC1) U33.1(CC1) U35.4(D2+) U35.7(NC)
USBTYPEC_CC2: J14.B5(CC2) U33.2(CC2) U35.5(D2-) U35.6(NC)
NetC125_2: C125.2 C127.1 D18.2 J14.A4(VBUS) J14.A9(VBUS) J14.B4(VBUS) J14.B9(VBUS) L9.1
NetC134_2: C134.2 U37.6(CT)
NetD19_1: D19.1(K) R143.2
NetR133_1: R133.1 U34.7(SEL2)
NetTP8_1: TP8.1 U33.9(ID)
NetTP9_1: TP9.1 U33.5(ADDR)

Not connected (* = marked no-connect by the designer): J14 A2(SSTXp1)* A3(SSTXn1)* A8(SBU1)* A10(SSRXn2)* A11(SSRXp2)* B2(SSTXp2)* B3(SSTXn2)* B8(SBU2)* B10(SSRXn1)* B11(SSRXp1)*; U34 6(L)* 12(R)*; U36 1(D1+)* 10(NC)*

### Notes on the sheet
- USB Type-AB
- USB Type-C Power Input: 5.0V, 3.1A
- USB Type-C CC Logic Controller
- (near R132) USB 2.0 MUX to USB-C / USB-AB
- (near U35) USB-C Protection
- USB-AB Protection
- USB 5.0V Input Power Load Switch (4A max)
- USB micro AB Power-Distribution Switch
- (near U39) Input Power Load Switch Enable
- PCB label: PWR failure

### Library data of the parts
C125 C126 C130 C131 C135 = CMP-0096736-1: 10 µF ±20% 25V Ceramic Capacitor X5R 0603 (1608 Metric); Manufacturer: Wurth; Cap_F: 10µF; AEC Qualified: No; SizeZ_mm: 1mm; Value: 10µF; TempCo: 15%
C127 C128 C132 C133 C137 = CMP-0006618-2: CAP, CERM, 0.1 uF, 100 V, +/- 10%, X5R, 0402; Manufacturer: MuRata; TaMin_C: -55°C; Polarized: N; SizeAreaWB_mm2: 3; Value1: Unknown; U/M: EA; Value: 0.1uF; TaMax_C: 85°C; SizeZ_mm: 0.6; SizeX_mm: 1; SizeY_mm: 0.5; Cap_Case: 0402; Cap_F: 100nF; AEC Category: Q200
C129 C138 = CMP-0009293-2: CAP, CERM, 1000 pF, 2000 V, +/- 10%, X7R, 1812; Manufacturer: AVX; TaMin_C: -55°C; Polarized: N; SizeAreaWB_mm2: 23.1; Value1: Unknown; U/M: EA; Value: 1000pF; TaMax_C: 125°C; SizeZ_mm: 2.54; SizeX_mm: 4.5; SizeY_mm: 3.2; Cap_Case: 1812; Value2: 2000V; SizeArea_mm2: 14.4; Cap_F: 1nF; AEC Category: Q200
C134 = CMP-0006354-2: CAP, CERM, 1000 pF, 50 V, +/- 10%, X7R, AEC-Q200 Grade 1, 0402; Manufacturer: MuRata; TaMin_C: -55°C; Polarized: N; SizeAreaWB_mm2: 3; Value1: Unknown; U/M: EA; Value: 1000pF; TaMax_C: 125°C; SizeZ_mm: 0.6; SizeX_mm: 1; SizeY_mm: 0.5; Cap_Case: 0402; AEC Qualified: Y; Cap_F: 1nF; AEC Category: Q200
C136 = CMP-0006618-2: CAP, CERM, 0.1 uF, 100 V, +/- 10%, X5R, 0402; Manufacturer: MuRata; TaMin_C: -55°C; Polarized: N; SizeAreaWB_mm2: 3; Value1: Unknown; U/M: EA; Value: 0.1uF; TaMax_C: 85°C; SizeZ_mm: 0.6; SizeX_mm: 1; SizeY_mm: 0.5; Cap_F: 100nF; AEC Category: Q200
D18 = CMP-0005599-2: Diode, TVS, Bi, 6.5 V, SMB; Manufacturer: Littelfuse; SizeZ_mm: 2.6; SizeY_mm: 3.81; Ppk: 600W; AEC Category: Q101; RJA_CperW: 100; SizeArea_mm2: 21.336; SizeX_mm: 5.6; SizeAreaWB_mm2: 44.156
D19 = CMP-0002947-3: LED, Red, SMD; Manufacturer: Wurth Elektronik; Value1: 0.072W; Vf_V: 2V; Angle: 140; Tjmax_C: 85°C; Type: AlInGaP; Vr_V: 5V; Io_A: 30mA; Power_TotalModule: 72mW
J13 = CMP-0097752-1: Conn Micro USB 2.0 Type AB RCP 5 POS 0.65mm Solder RA SMD 5 Terminal 1 Port T/R; Manufacturer: Wurth Electronics; Shrouded: true; Voltage_V: 30V; Usb Standard: USB 2.0; Current_A: 1A; ContactFinish: Gold; SizeZ_mm: 3.2mm; Is Female: yes; Conn Orientation: Horizontal; AEC Qualified: No
J14 = CMP-0091586-1: USB-C (USB TYPE-C) USB 3.2 Gen 2 (USB 3.1 Gen 2, Superspeed + (USB 3.1)) Receptacle Connector 24 Position Surface Mount, Right Angle; Through Hole; Manufacturer: Wurth; AEC Qualified: No; Shrouded: true; SizeZ_mm: 3.41mm; Is Female: yes; Usb Standard: USB 3.1; Voltage_V: 20V; ContactFinish: Gold,Nickel; Conn Orientation: Horizontal; Standoff Height: 0.1mm; Current_A: 5A
J20 = CMP-0054794-2: as J5 on sheet TIDA-010973_SystemLED
L9 = CMP-0003091-1: Ferrite Bead, 30 ohm @ 100 MHz, 3 A, 0805; Manufacturer: Wurth Elektronik; Ztyp@1GHz_Ohm: 71.201; ZTyp@100MHz_Ohm: 30; SizeAreaWB_mm2: 6.75; DCR_ohm: 0.025; Value1: 0.025 ohm; Value: 30 ohm; Imax_A: 3A; SizeZ_mm: 1.45; SizeX_mm: 2; SizeY_mm: 1.25; SizeArea_mm2: 2.5
L10 L11 = CMP-0125765-1: 2 Line Common Mode Choke Surface Mount 90 Ohms @ 100 MHz 280mA DCR 300mOhm; Manufacturer: Wurth; AEC Grade: Grade 2; AEC Qualified: Yes; DCR_ohm: 0.3; Ind_H: 131nH; SizeZ_mm: 1.4mm; Impedance At Frequency: 90Ω @ 100MHz; TaMax_C: +85°C; TaMin_C: -40°C; Voltage: 50V
R132 = CMP-0025967-3: RES, 110 k, 1%, 0.063 W, AEC-Q200 Grade 0, 0402; Manufacturer: Vishay-Dale; Power_W: 63mW; TempCo: 100 ppm/C; Value: 110k; EIA_Code: E96; SizeY_mm: 0.5; SizeZ_mm: 0.6; Value2: 0.063W; AEC Qualified: Y; VDC_V: 50V; AEC Category: Q200; SizeX_mm: 1; AEC Grade: 0
R133 R134 R136 R137 R140-R142 = CMP-0025958-3: as R12 on sheet TIDA-010973_SystemLED
R135 = CMP-0026158-2: RES, 200 k, 1%, 0.063 W, AEC-Q200 Grade 0, 0402; Manufacturer: Vishay-Dale; Power_W: 63mW; TempCo: 100 ppm/C; Value: 200k; EIA_Code: E96; SizeX_mm: 1; SizeY_mm: 0.5; SizeZ_mm: 0.6; Value2: 0.063W; AEC Qualified: Y; VDC_V: 50V; AEC Category: Q200; AEC Grade: 0
R138 = CMP-0026603-2: RES, 909 k, 1%, 0.063 W, AEC-Q200 Grade 0, 0402; Manufacturer: Vishay-Dale; Power_W: 63mW; TempCo: 100 ppm/C; Value: 909k; EIA_Code: E96; SizeX_mm: 1; SizeY_mm: 0.5; SizeZ_mm: 0.6; Value2: 0.063W; AEC Qualified: Y; VDC_V: 50V; AEC Category: Q200; AEC Grade: 0
R139 R144 = CMP-0016296-3: RES, 1.00 M, 1%, 0.75 W, AEC-Q200 Grade 0, 2010; Manufacturer: Vishay-Dale; Power_W: 750mW; TempCo: 100 ppm/C; Value_Code: 1M00; Value: 1.00Meg; EIA_Code: E96; Res_ohm: 1M; SizeX_mm: 5; SizeY_mm: 2.5; SizeZ_mm: 1.66; Value2: 0.75W; SizeArea_mm2: 12.5; AEC Qualified: Y; VDC_V: 400V; AEC Grade: 0; AEC Category: Q200
R143 = CMP-0026534-2: RES, 715, 1%, 0.063 W, AEC-Q200 Grade 0, 0402; Manufacturer: Vishay-Dale; Power_W: 63mW; TempCo: 100 ppm/C; Value_Code: 715R; Value: 715; EIA_Code: E96; SizeX_mm: 1; SizeY_mm: 0.5; SizeZ_mm: 0.6; Value2: 0.063W; AEC Qualified: Y; VDC_V: 50V; AEC Category: Q200; AEC Grade: 0
TP8 TP9 = CMP-0078143-4: TEST POINT.  No entry in BOM.
U33 = CMP-0073635-2: USB Type-C Configuration Channel Logic and Port Control, RWB0012A (X2QFN-12); Alternate Manufacturer: Texas Instruments; SizeAreaWB_mm2: 6.76; SizeZ_mm: 0.4; SizeX_mm: 1.6; SizeArea_mm2: 2.56; CompType: IC; AEC Category: Q200; AEC Qualified: N; Rating: Catalog
U34 = CMP-0033722-2: USB 2.0 High-Speed (480 Mbps) and Audio Switch, DP3T, 6.5 ohm RON, -40 to 85 degC, 12-Pin UQFN (RUT), Green (RoHS & no Sb/Br); Manufacturer: Texas Instruments; ICC(uA): 25; OFF Time(Max)(ns): 20; IL OFF(Max)(nA): +/-1000; Vcc range(V): 2.7 to 4.3; ON Time(Max)(ns): 60; RON Mis-match(Max)(Ohms): 0.1; SubFamily: USB Switch; ESD HBM(kV): 2; Number of Channels: 3; Bandwidth(MHz): 1900
U35 U36 = CMP-0073612-3: 4-Channel ESD Protection Diode for USB Type-C and HDMI 2.0, DQA0010A (USON-10); Alternate Manufacturer: Texas Instruments; Green_Lifecycle: Active; SizeAreaWB_mm2: 7.0; Green_REACh: Passed; SizeZ_mm: 0.55; SizeX_mm: 1.0; SizeY_mm: 2.5; CompType: IC; AEC Category: Q200; AEC Qualified: Y
U37 = CMP-0073678-3: 5.5V, 4A, 16mΩ Automotive Load Switch With Adjustable Rise Time and Optional Quick Output Discharge, DSG0008B (WSON-8); Alternate PartNumber: TPS22965TDSGTQ1; Alternate Manufacturer: Texas Instruments; Green_Lifecycle: Active; SizeAreaWB_mm2: 9.0; Green_REACh: Passed; U/M: EA; SizeZ_mm: 0.8; SizeX_mm: 2.0; SizeArea_mm2: 4.0; CompType: IC; AEC Category: Q200; AEC Qualified: Y
U38 = CMP-0074276-1: Single, Current-Limited, Power-Distribution Switch, DBV0005A (SOT-23-5); Alternate PartNumber: TPS2051BDBVT; Alternate Manufacturer: Texas Instruments; Green_Lifecycle: Active; SizeAreaWB_mm2: 14.82; Green_REACh: Passed; U/M: EA; SizeZ_mm: 1.45; SizeX_mm: 2.8; SizeY_mm: 2.9; SizeArea_mm2: 8.12; CompType: IC
U39 = CMP-0051530-2: Single 2-Input Positive-NOR Gate, DRL0005A, LARGE T&R; Manufacturer: Texas Instruments; Schmitt Trigger: No; Technology Family: AHC; Logic: True; Gate Type: NOR; Output Type: CMOS; Sub-Family: NAND Gate; Rating: Catalog; F @ Nom Voltage(Max)(Mhz): 75; ICC @ Nom Voltage(Max)(mA): 0.01; tpd @ Nom Voltage(Max)(ns): 11.4,7.5; Voltage(Nom)(V): 3.3,5; Output Drive (IOL/IOH)(Max)(mA): 50/-50; VCC(Max)(V): 5.5; VCC(Min)(V): 2; Bits(#): 1; AEC Category: Q200; AEC Qualified: N; CompType: IC; SizeArea_mm2: 2.56; SizeX_mm: 1.6; SizeZ_mm: 0.6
